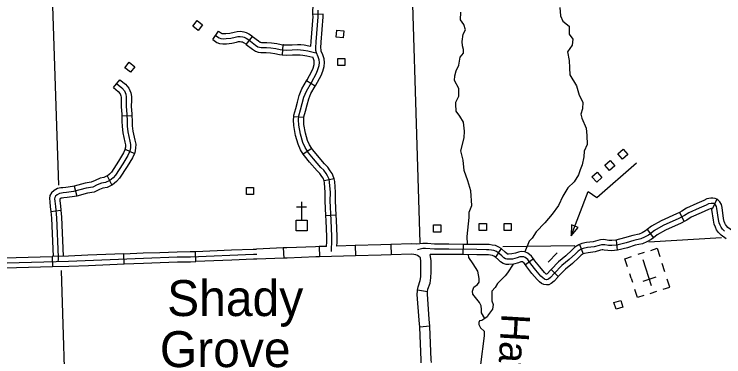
# Model space of a CAD drawing. Extents: x 155 to 3386, y 68 to 2138.
# Drawn here: x 1855.9 to 2154, y 551.2 to 695.1 of the extents above; entities that cross this region are included whole.
import ezdxf

# ---------------------------------------------------------------- set-up
doc = ezdxf.new("R2010")
doc.units = 0
for name, color, linetype in [('Level 24', 7, 'Continuous'), ('Level 31', 7, 'Continuous'), ('Level 32', 7, 'Continuous'), ('Level 35', 7, 'Continuous'), ('Level 5', 7, 'Continuous'), ('Level 56', 7, 'Continuous'), ('Level 57', 7, 'Continuous')]:
    doc.layers.add(name, color=color, linetype=linetype)

msp = doc.modelspace()

# ---------------------------------------------------------------- linework, layer by layer
at = {"layer": 'Level 31'}
for p, q in [((1871.81, 593.39), (1871.92, 589.11)), ((1902.1, 590.24), (1901.93, 594.52)), ((1901.93, 594.52), (1901.93, 594.52)), ((1932.26, 591.21), (1932.09, 595.5))]:
    msp.add_line(p, q, dxfattribs=at)
for points in [[(1797.31, 667.31), (1798.16, 646.01), (1799.06, 609.19), (1799.39, 589), (1803.2, 589.28), (1816.86, 589.87), (1832.07, 590.19), (1878.76, 591.43), (1910.14, 592.71), (1924.39, 593.22), (1929.89, 593.26), (1956.37, 594.32), (1957.8, 594.37)], [(1947.16, 596.1), (1956.29, 596.46), (1957.71, 596.51)], [(1856.73, 592.99), (1871.81, 593.39)], [(1886.86, 593.91), (1878.68, 593.57), (1871.81, 593.39)], [(1901.93, 594.52), (1886.86, 593.91)], [(1901.93, 594.52), (1910.06, 594.85), (1917.02, 595.1)], [(1917.02, 595.1), (1924.34, 595.36), (1929.84, 595.41), (1932.09, 595.5)], [(1932.09, 595.5), (1947.16, 596.1)], [(1841.65, 592.59), (1856.73, 592.99)], [(1902.1, 590.24), (1910.22, 590.57), (1917.17, 590.82)], [(1917.17, 590.82), (1924.44, 591.08), (1929.94, 591.12), (1932.26, 591.21)], [(1947.33, 591.81), (1932.26, 591.21)], [(1957.88, 592.23), (1956.46, 592.18), (1947.33, 591.81)], [(1841.76, 588.31), (1856.84, 588.71)], [(1856.84, 588.71), (1871.92, 589.11)], [(1871.92, 589.11), (1878.83, 589.29), (1887.03, 589.62)], [(1887.03, 589.62), (1902.1, 590.24)]]:
    msp.add_lwpolyline(points, dxfattribs=at)
at = {"layer": 'Level 32'}
for p, q in [((1985.7, 695.14), (1981.42, 695.08)), ((1939.3, 684.45), (1941.71, 687.99)), ((1953.39, 682.46), (1956.03, 685.83)), ((1968.67, 678.03), (1968.89, 682.31)), ((1897.54, 664.33), (1900.28, 667.63)), ((1982.4, 664.92), (1978.71, 667.1)), ((1901.07, 652.4), (1905.35, 652.55)), ((1977.62, 651.78), (1973.34, 652.09)), ((1902.49, 638.45), (1906.39, 636.68)), ((1980.96, 638.72), (1977.35, 636.42)), ((1895, 627.21), (1896.87, 623.36)), ((1990.3, 626.06), (1986.11, 625.19)), ((1881.08, 622.92), (1882.15, 618.77)), ((2151.04, 617.42), (2149.3, 613.51)), ((1871.25, 612.33), (1875.51, 612.76)), ((2135.45, 611.91), (2137.44, 608.11)), ((1991.12, 610.69), (1986.84, 610.47)), ((2121.85, 604.67), (2124.46, 601.27)), ((2108.83, 600.24), (2109.2, 595.97)), ((1968.94, 596.95), (1969.11, 592.67)), ((1984.04, 597.51), (1984.16, 593.23)), ((1999.12, 597.92), (1999.24, 593.63)), ((2014.19, 598.34), (2014.33, 594.06)), ((2044.47, 598.46), (2044.43, 594.17)), ((2060.46, 596.69), (2058.06, 593.14)), ((2093.4, 598.46), (2094.96, 594.47)), ((2074.09, 592.4), (2070.68, 589.8)), ((2081.43, 587.95), (2084.49, 584.94)), ((2029.56, 578.56), (2025.33, 579.28)), ((2030.54, 564.09), (2026.28, 563.66))]:
    msp.add_line(p, q, dxfattribs=at)
for points in [[(1981.42, 695.08), (1981.39, 697.01), (1981.8, 699.97), (1982.19, 701.79), (1982.87, 703.41), (1983.85, 705.04), (1986.16, 708.56), (1987.27, 710.04)], [(1989.21, 595.51), (1989.2, 596.47), (1989.36, 599.46), (1989.36, 601.73), (1989.08, 608.56), (1988.67, 616.75), (1988.71, 620.3), (1988.42, 624.6), (1988.17, 625.81), (1987.54, 627.23), (1986.91, 628.19), (1986, 629.57), (1984.74, 630.78), (1981.61, 634.41), (1979.57, 636.92), (1978.11, 639.22), (1977.15, 641.31), (1976.14, 644.69), (1975.48, 648.57), (1975.39, 650.71), (1975.52, 652.42), (1976.23, 655.01), (1976.94, 657.64), (1977.6, 660.28), (1978.65, 662.78), (1980.82, 666.46), (1982.95, 670.34), (1983.49, 671.85), (1983.99, 673.57), (1984.12, 674.86), (1984.03, 675.95), (1983.57, 677.24), (1982.85, 678.91), (1982.66, 679.87), (1982.61, 681), (1982.78, 683.59), (1983.57, 694.07), (1983.53, 696.88)], [(1980.51, 681.68), (1980.64, 683.74), (1981.43, 694.14), (1981.42, 695.08)], [(1984.79, 680.14), (1984.76, 680.97), (1984.92, 683.44), (1985.72, 694.01), (1985.7, 695.14)], [(1940.51, 686.22), (1942, 685.21), (1942.66, 684.98), (1943.67, 684.85), (1944.98, 684.87), (1946.9, 685.11), (1948.74, 685.54), (1949.81, 685.78), (1950.87, 685.83), (1951.89, 685.7), (1952.55, 685.49), (1953.36, 685.09), (1954.4, 684.39), (1957.22, 682.18), (1958.26, 681.48), (1958.93, 681.24), (1959.63, 681.16), (1960.27, 681.16), (1961.9, 681.16), (1963.74, 681), (1965.79, 680.76), (1967.69, 680.33), (1968.75, 680.17), (1970.3, 680.09), (1972.7, 680.2), (1974.92, 680.25), (1976.12, 680.23), (1977.45, 680.09), (1979.21, 679.77), (1980.87, 679.4), (1982.12, 679.05), (1982.85, 678.91)], [(1941.71, 687.99), (1942.97, 687.14), (1943.15, 687.08), (1943.79, 686.99), (1944.82, 687.01), (1946.52, 687.23), (1948.26, 687.63), (1949.52, 687.91), (1950.96, 687.98), (1952.36, 687.8), (1953.37, 687.48), (1954.43, 686.94), (1955.65, 686.13), (1956.03, 685.83)], [(1956.03, 685.83), (1958.48, 683.91), (1959.24, 683.41), (1959.42, 683.34), (1959.75, 683.3), (1960.27, 683.3), (1961.99, 683.3), (1963.96, 683.13), (1966.16, 682.88), (1968.08, 682.44), (1968.97, 682.31), (1968.89, 682.31)], [(1939.3, 684.45), (1941.03, 683.27), (1942.16, 682.88), (1943.55, 682.7), (1945.13, 682.73), (1947.27, 683), (1949.22, 683.45), (1950.1, 683.65), (1950.79, 683.68), (1951.42, 683.6), (1951.74, 683.5), (1952.28, 683.23), (1953.14, 682.65), (1953.39, 682.46)], [(1953.39, 682.46), (1955.97, 680.44), (1957.29, 679.55), (1958.44, 679.14), (1959.5, 679.02), (1960.27, 679.02), (1961.81, 679.02), (1963.52, 678.87), (1965.43, 678.65), (1967.29, 678.23), (1968.54, 678.04), (1968.67, 678.03)], [(1968.89, 682.31), (1970.31, 682.24), (1972.63, 682.34), (1974.92, 682.4), (1976.25, 682.37), (1977.75, 682.22), (1979.64, 681.87), (1980.51, 681.68)], [(1982.4, 664.92), (1982.68, 665.4), (1984.91, 669.46), (1985.53, 671.18), (1986.1, 673.16), (1986.27, 674.84), (1986.15, 676.4), (1985.57, 678.03), (1984.91, 679.56), (1984.79, 680.13), (1984.79, 680.14)], [(1968.67, 678.03), (1970.29, 677.95), (1972.78, 678.06), (1974.92, 678.11), (1975.99, 678.09), (1977.15, 677.97), (1978.79, 677.67), (1981.3, 677.11)], [(1978.71, 667.1), (1978.96, 667.52), (1980.99, 671.23), (1981.45, 672.51), (1981.88, 673.97), (1981.97, 674.88), (1981.92, 675.5), (1981.58, 676.46), (1981.3, 677.11)], [(1898.91, 665.98), (1901.1, 664.17), (1902.17, 662.89), (1902.81, 661.5), (1902.97, 660.43), (1902.97, 659.09), (1902.91, 656.32), (1903.18, 653.22), (1903.29, 650.23), (1903.34, 648.15), (1903.66, 645.69), (1904.52, 641.85), (1904.78, 640.44), (1904.73, 639.05), (1904.46, 637.61), (1903.66, 635.85), (1901.47, 632.27), (1898.43, 627.52), (1897.42, 626.4), (1896.03, 625.33), (1894.27, 624.48), (1892.56, 624.16), (1890.8, 623.41), (1888.88, 622.5), (1886.16, 622.02), (1880.77, 620.63), (1877.89, 620.24), (1876.5, 620.08), (1875.7, 620.03), (1874.9, 619.87), (1873.99, 619.33), (1873.24, 618.69), (1872.98, 618.21), (1872.87, 617.57), (1872.92, 616.56), (1873.19, 614.42), (1873.67, 609.67), (1874.36, 593.08), (1874.31, 592.12), (1874.26, 591.31)], [(1900.28, 667.63), (1902.62, 665.69), (1903.99, 664.04), (1904.88, 662.12), (1905.11, 660.59), (1905.11, 659.07), (1905.06, 656.39), (1905.32, 653.35), (1905.35, 652.55)], [(1973.34, 652.09), (1973.4, 652.79), (1974.16, 655.58), (1974.86, 658.19), (1975.57, 660.96), (1976.73, 663.74), (1978.71, 667.1)], [(1977.62, 651.78), (1977.64, 652.06), (1978.29, 654.45), (1979.01, 657.1), (1979.64, 659.6), (1980.57, 661.82), (1982.4, 664.92)], [(1897.54, 664.33), (1899.58, 662.64), (1900.34, 661.73), (1900.73, 660.88), (1900.83, 660.27), (1900.83, 659.12), (1900.77, 656.25), (1901.04, 653.09), (1901.07, 652.4)], [(1901.07, 652.4), (1901.15, 650.17), (1901.2, 647.98), (1901.55, 645.32), (1902.42, 641.42), (1902.63, 640.28), (1902.59, 639.29), (1902.4, 638.26), (1902.49, 638.45)], [(1905.35, 652.55), (1905.43, 650.3), (1905.48, 648.32), (1905.77, 646.06), (1906.61, 642.28), (1906.93, 640.6), (1906.86, 638.81), (1906.52, 636.96), (1906.39, 636.68)], [(1977.35, 636.42), (1976.22, 638.19), (1975.13, 640.55), (1974.05, 644.2), (1973.34, 648.35), (1973.25, 650.75), (1973.34, 652.09)], [(1980.96, 638.72), (1979.99, 640.24), (1979.16, 642.06), (1978.23, 645.18), (1977.61, 648.8), (1977.54, 650.68), (1977.62, 651.78)], [(1902.49, 638.45), (1901.76, 636.85), (1899.66, 633.41), (1896.72, 628.82), (1895.96, 627.98), (1894.9, 627.16), (1895, 627.21)], [(1990.3, 626.06), (1990.22, 626.47), (1989.43, 628.25), (1988.7, 629.37), (1987.65, 630.95), (1986.3, 632.25), (1983.25, 635.79), (1981.31, 638.18), (1980.96, 638.72)], [(1906.39, 636.68), (1905.56, 634.84), (1903.29, 631.13), (1900.14, 626.21), (1898.88, 624.82), (1897.16, 623.5), (1896.87, 623.36)], [(1986.11, 625.15), (1985.65, 626.21), (1985.12, 627.01), (1984.34, 628.19), (1983.18, 629.31), (1979.97, 633.04), (1977.83, 635.66), (1977.35, 636.42)], [(1895, 627.21), (1893.59, 626.53), (1891.94, 626.22), (1889.92, 625.36), (1888.22, 624.56), (1885.7, 624.12), (1881.08, 622.92)], [(1896.87, 623.36), (1894.95, 622.42), (1893.18, 622.09), (1891.68, 621.45), (1889.53, 620.44), (1886.61, 619.92), (1882.15, 618.77)], [(1986.84, 610.47), (1986.52, 616.7), (1986.57, 620.24), (1986.29, 624.31), (1986.11, 625.19)], [(1991.12, 610.69), (1990.81, 616.79), (1990.85, 620.36), (1990.54, 624.89), (1990.3, 626.06)], [(1881.08, 622.92), (1880.36, 622.74), (1877.62, 622.37), (1876.3, 622.22), (1875.41, 622.16), (1874.12, 621.9), (1872.74, 621.09), (1871.56, 620.07), (1870.92, 618.93), (1870.72, 617.69), (1870.79, 616.37), (1871.06, 614.18), (1871.25, 612.33)], [(1882.15, 618.77), (1881.18, 618.53), (1878.15, 618.12), (1876.69, 617.95), (1875.98, 617.9), (1875.67, 617.84), (1875.24, 617.58), (1875.02, 617.4), (1875.06, 616.75), (1875.32, 614.66), (1875.51, 612.76)], [(2151.04, 617.42), (2150.34, 617.73), (2149.43, 617.84), (2148.57, 617.84), (2146.95, 617.57), (2145.68, 616.9), (2142.75, 615.61), (2138.29, 613.61), (2136.38, 612.39), (2135.45, 611.91)], [(2157.63, 604.1), (2155.77, 605.56), (2155.14, 606.21), (2154.71, 606.83), (2154.43, 607.36), (2154.2, 608.05), (2153.95, 609.3), (2153.28, 613.94), (2153, 615.19), (2152.31, 616.32), (2151.55, 617.2), (2151.04, 617.42)], [(2154.34, 603.96), (2153.49, 604.84), (2152.87, 605.71), (2152.46, 606.51), (2152.12, 607.49), (2151.84, 608.94), (2151.17, 613.55), (2150.99, 614.38), (2150.58, 615.05), (2150.24, 615.44), (2149.78, 615.64), (2149.31, 615.69), (2148.75, 615.69), (2147.64, 615.51), (2146.61, 614.97), (2143.62, 613.66), (2139.31, 611.72), (2137.46, 610.54), (2135.14, 609.32), (2128.62, 606.36), (2124.88, 604.3), (2122.33, 602.34), (2120.76, 601.43), (2119.19, 600.74), (2116.27, 600.15), (2112.95, 599.11), (2109.06, 598.11), (2106.97, 597.93), (2105.53, 598.01), (2104.03, 598.21), (2103.31, 598.31), (2102.59, 598.26), (2101.64, 598.03), (2099.57, 597.41), (2096.71, 597.08), (2094.96, 596.77), (2094.03, 596.41), (2092.82, 595.63), (2091.69, 594.52), (2089.03, 592.07), (2086.04, 589.57), (2082.74, 586.22), (2081.28, 584.6), (2080.35, 583.82), (2079.94, 583.64), (2079.55, 583.62), (2079.03, 583.67), (2078.67, 583.88), (2078.03, 584.37), (2077.2, 585.16), (2075.06, 587.61), (2073, 590.3), (2071.66, 592.05), (2070.63, 592.95), (2069.96, 593.21), (2069.03, 593.26), (2068.26, 593.16), (2067.18, 592.77), (2065.3, 592.31), (2063.6, 592.18), (2062.85, 592.2), (2062.26, 592.36), (2061.61, 592.82), (2060.79, 593.62), (2059.27, 594.91), (2058.47, 595.45), (2057.46, 595.87), (2056.41, 596.07), (2055.32, 596.2), (2054.34, 596.2), (2050.3, 596.25), (2038.55, 596.38), (2032.41, 596.41), (2028.75, 596.66), (2027.64, 596.66), (2026.43, 596.51), (2025.31, 596.17)], [(1871.25, 612.33), (1871.53, 609.52), (1872.21, 593.4)], [(1875.51, 612.76), (1875.81, 609.82), (1876.49, 593.51)], [(2135.45, 611.91), (2134.2, 611.25), (2127.66, 608.28), (2123.7, 606.09), (2121.85, 604.67)], [(2149.3, 613.51), (2149.21, 613.55), (2149.19, 613.55), (2148.92, 613.55), (2148.33, 613.45), (2147.54, 613.04), (2144.49, 611.7), (2140.33, 609.83), (2138.53, 608.68), (2137.44, 608.11)], [(2154.99, 600.73), (2152.9, 602.37), (2151.83, 603.47), (2151.03, 604.6), (2150.48, 605.67), (2150.05, 606.94), (2149.73, 608.58), (2149.06, 613.17), (2148.97, 613.57), (2148.9, 613.69), (2149.3, 613.51)], [(1987.12, 597.6), (1987.22, 599.52), (1987.22, 601.68), (1986.94, 608.46), (1986.84, 610.47)], [(1991.42, 597.71), (1991.51, 599.4), (1991.51, 601.77), (1991.23, 608.66), (1991.12, 610.69)], [(2137.44, 608.11), (2136.08, 607.4), (2129.58, 604.44), (2126.06, 602.5), (2124.46, 601.27)], [(2121.85, 604.67), (2121.14, 604.12), (2119.79, 603.35), (2118.53, 602.79), (2115.74, 602.22), (2112.36, 601.18), (2108.69, 600.23), (2108.83, 600.24)], [(2108.83, 600.24), (2106.93, 600.08), (2105.73, 600.14), (2104.33, 600.33), (2103.39, 600.47), (2102.26, 600.39), (2101.07, 600.1), (2099.14, 599.52), (2096.4, 599.2), (2094.38, 598.84), (2093.4, 598.46)], [(2124.46, 601.27), (2123.52, 600.55), (2121.73, 599.52), (2119.84, 598.69), (2116.81, 598.07), (2113.53, 597.05), (2109.42, 595.99), (2109.2, 595.97)], [(1968.94, 596.95), (1957.71, 596.51)], [(1984.04, 597.51), (1982.45, 597.47), (1970.45, 597.01), (1968.94, 596.95)], [(1987.12, 597.6), (1984.04, 597.51)], [(1999.12, 597.92), (1991.42, 597.71)], [(2014.19, 598.34), (2009.92, 598.21), (1999.12, 597.92)], [(2024.99, 598.49), (2022.9, 598.62), (2014.19, 598.34)], [(2029.52, 598.76), (2028.83, 598.81), (2027.51, 598.81), (2024.99, 598.49)], [(2044.47, 598.46), (2038.56, 598.52), (2032.49, 598.55), (2029.52, 598.76)], [(2060.46, 596.69), (2059.49, 597.35), (2058.08, 597.93), (2056.74, 598.19), (2055.45, 598.34), (2054.36, 598.34), (2050.32, 598.39), (2044.47, 598.46)], [(2074.09, 592.4), (2073.24, 593.52), (2071.76, 594.81), (2070.42, 595.33), (2068.95, 595.41), (2067.75, 595.25), (2066.56, 594.83), (2064.96, 594.43), (2063.55, 594.32), (2063.18, 594.34), (2062.99, 594.47), (2062.23, 595.21), (2060.56, 596.62), (2060.46, 596.69)], [(2093.4, 598.46), (2093.06, 598.33), (2091.48, 597.32), (2090.21, 596.08), (2087.62, 593.69), (2084.59, 591.15), (2081.43, 587.95)], [(1999.24, 593.63), (1984.16, 593.23)], [(2014.33, 594.06), (2010.05, 593.93), (1999.24, 593.63)], [(2026.57, 592.75), (2025.95, 593.34), (2025.29, 593.8), (2024.64, 594.11), (2023.8, 594.27), (2022.83, 594.33), (2014.33, 594.06)], [(2029.56, 578.56), (2029.74, 579.62), (2030.6, 582.23), (2030.99, 584.41), (2031.04, 586.92), (2031.01, 591.53), (2030.71, 594.27)], [(2044.43, 594.17), (2038.53, 594.24), (2030.71, 594.27)], [(2058.06, 593.14), (2057.45, 593.55), (2056.84, 593.8), (2056.07, 593.95), (2055.2, 594.06), (2054.33, 594.06), (2050.27, 594.11), (2044.43, 594.17)], [(2095.01, 594.49), (2094.16, 593.95), (2093.16, 592.97), (2090.45, 590.46), (2087.5, 588), (2084.49, 584.94)], [(2109.2, 595.97), (2107, 595.78), (2105.32, 595.87), (2103.73, 596.09), (2103.23, 596.16), (2102.92, 596.14), (2102.2, 595.96), (2100.01, 595.31), (2097.02, 594.96), (2095.54, 594.69), (2094.96, 594.47)], [(1969.11, 592.67), (1957.88, 592.23)], [(1984.16, 593.23), (1982.59, 593.19), (1970.61, 592.73), (1969.11, 592.67)], [(2025.33, 579.28), (2025.57, 580.66), (2026.43, 583.29), (2026.71, 584.83), (2026.76, 586.96), (2026.73, 591.28), (2026.57, 592.75)], [(2070.68, 589.8), (2070.09, 590.58), (2069.51, 591.09), (2069.51, 591.09), (2069.12, 591.11), (2068.77, 591.06), (2067.8, 590.72), (2065.64, 590.18), (2063.64, 590.03), (2062.54, 590.07), (2061.33, 590.39), (2060.23, 591.18), (2059.35, 592.03), (2057.97, 593.2), (2058.06, 593.14)], [(2081.43, 587.95), (2081.19, 587.69), (2079.79, 586.15), (2079.52, 585.92), (2079.43, 585.99), (2078.76, 586.64), (2076.72, 588.97), (2074.7, 591.6), (2074.09, 592.4)], [(2084.49, 584.94), (2084.3, 584.75), (2082.76, 583.05), (2081.49, 581.98), (2080.45, 581.53), (2079.51, 581.47), (2078.37, 581.58), (2077.49, 582.08), (2076.63, 582.74), (2075.65, 583.69), (2073.41, 586.26), (2071.3, 588.99), (2070.68, 589.8)], [(2026.28, 563.66), (2025.97, 566.67), (2025.23, 577.44), (2025.29, 579.01), (2025.33, 579.28)], [(2030.54, 564.09), (2030.24, 567.04), (2029.52, 577.51), (2029.56, 578.57), (2029.56, 578.56)], [(2026.89, 548.75), (2026.86, 549.77), (2026.28, 563.67), (2026.28, 563.66)], [(2031.17, 548.86), (2031.14, 549.92), (2030.55, 563.98), (2030.54, 564.09)]]:
    msp.add_lwpolyline(points, dxfattribs=at)
at = {"layer": 'Level 35'}
for points in [[(2085.14, 697.94), (2085.4, 694.5), (2086.41, 692.27), (2089.04, 690.15), (2089.04, 686.81), (2090.55, 684.69), (2090.35, 682.16), (2088.33, 679.38), (2089.04, 675.64), (2089.14, 672.6), (2089.34, 669.67), (2092.17, 665.12), (2093.28, 661.18), (2094.79, 658.25), (2094.69, 655.42), (2093.99, 653.09), (2094.39, 651.48), (2096.21, 647.28), (2096.51, 644.25), (2096.61, 640.41), (2095.39, 637.67), (2095.2, 635.25), (2094.51, 631.94), (2093.64, 629.82), (2093.02, 627.71), (2091.2, 624.78), (2088.53, 622.21), (2086.41, 618.72), (2084.54, 614.73), (2081.86, 611.2), (2078.8, 607.5), (2075.16, 603.77), (2073.56, 601.1), (2072.26, 599.77), (2070.42, 595.33)], [(2045.09, 646.01), (2044.68, 649.75), (2043.07, 652.28), (2041.55, 654.4), (2041.45, 657.33), (2041.45, 658.14), (2042.66, 660.77), (2042.76, 664), (2040.84, 667.27), (2041.05, 669.19), (2041.55, 671.41), (2042.66, 673.74), (2043.29, 677.05), (2044.61, 678.71), (2044.61, 680.38), (2044.3, 681.9), (2044.15, 683.67), (2044.51, 686.75), (2045.47, 688.62), (2044.76, 690.79), (2043.39, 692.71), (2043.6, 696)], [(2046.32, 598.59), (2046.2, 601.8), (2047.01, 609.68), (2047.11, 612.01), (2048.12, 614.84), (2047.81, 620.94), (2046.5, 625.09), (2044.99, 629.43), (2044.48, 633.78), (2043.57, 637.72), (2044.99, 643.18), (2045.09, 646.01)], [(2065.49, 590.17), (2063.17, 586.53), (2062.16, 585.22), (2058.93, 582.09), (2057.92, 580.37), (2056.6, 578.85), (2056.6, 576.02), (2056.6, 574.71), (2057.11, 573.19), (2056.81, 571.27), (2055.19, 568.94), (2054.58, 568.04), (2053.57, 567.33), (2052.16, 569.75), (2052.16, 571.07), (2052.06, 572.58), (2051.45, 574), (2048.62, 577.54), (2048.42, 578.85), (2049.03, 580.47), (2050.54, 581.58), (2051.25, 582.59), (2051.25, 584.11), (2050.75, 587.14), (2048.72, 590.27), (2046.91, 593), (2046.75, 594.09)], [(2053.57, 567.33), (2052.36, 566.47), (2051.35, 566.37), (2051.1, 565.61), (2051.1, 564.85), (2051.85, 563.44), (2053.37, 561.97), (2053.37, 560.81), (2053.34, 560.11)], [(2053.34, 560.11), (2051.79, 547.94)]]:
    msp.add_lwpolyline(points, dxfattribs=at)
at = {"layer": 'Level 5'}
for points in [[(2021.71, 749.3), (2026.33, 599.15)], [(1870.6, 740.89), (1873.36, 656.54)], [(1873.36, 656.54), (1874.45, 623.3)], [(2122.47, 599.56), (2153.08, 601.31)], [(2061.21, 597.63), (2091.49, 598.04)], [(1875.61, 587.46), (1877.76, 519.78)]]:
    msp.add_lwpolyline(points, dxfattribs=at)
at = {"layer": 'Level 56'}
for points in [[(1933.2, 688.3), (1930.87, 690.14), (1932.72, 692.48), (1935.05, 690.64)], [(1991.41, 688.42), (1994.38, 688.19), (1994.15, 685.22), (1991.19, 685.44)], [(1902.36, 672.65), (1904.22, 674.97), (1906.55, 673.1), (1904.69, 670.78)], [(1991.83, 673.54), (1991.83, 676.52), (1994.81, 676.52), (1994.81, 673.54)], [(2111.47, 634.27), (2109.5, 636.5), (2111.73, 638.48), (2113.7, 636.25)], [(2105.98, 629.53), (2104.01, 631.76), (2106.24, 633.74), (2108.22, 631.51)], [(2100.62, 624.54), (2098.65, 626.77), (2100.88, 628.75), (2102.85, 626.52)], [(1953.46, 619.38), (1953.46, 622.36), (1956.44, 622.36), (1956.44, 619.38)], [(2032.1, 603.63), (2032.1, 606.6), (2035.08, 606.6), (2035.08, 603.63)], [(2051.3, 604.31), (2051.3, 607.28), (2054.28, 607.28), (2054.28, 604.31)], [(2061.68, 604.26), (2061.68, 607.24), (2064.66, 607.24), (2064.66, 604.26)], [(2092.81, 605.58), (2090.09, 606.61), (2089.9, 602.01)], [(2110.7, 574.94), (2111.64, 572.12), (2108.81, 571.18), (2107.87, 574)]]:
    msp.add_lwpolyline(points, close=True, dxfattribs=at)
for points in [[(2089.9, 602.01), (2097.01, 620.71), (2100.75, 618.09), (2117.32, 632.78)], [(2084.04, 594.9), (2080.3, 591.03)]]:
    msp.add_lwpolyline(points, dxfattribs=at)
at = {"layer": 'Level 57'}
for p, q in [((1974.48, 614.21), (1978.76, 614.21)), ((1976.62, 616.35), (1976.62, 608.66)), ((2120.63, 595.07), (2117.91, 594.2)), ((2123.66, 581.04), (2120.16, 591.92)), ((2129.25, 586.98), (2128.16, 590.38)), ((2115.11, 584.29), (2114.55, 586.02)), ((2125.5, 584.63), (2120.04, 582.87)), ((2121.91, 586.48), (2121.91, 586.48)), ((2121.91, 586.48), (2121.91, 586.48)), ((2115.11, 584.29), (2115.65, 582.62)), ((2123.15, 577.87), (2125.87, 578.75))]:
    msp.add_line(p, q, dxfattribs=at)
msp.add_lwpolyline([(1974.3, 604.2), (1974.3, 608.66), (1978.93, 608.66), (1978.93, 604.2)], close=True, dxfattribs=at)
for points in [[(2123.37, 595.95), (2126.09, 596.82), (2127.18, 593.42)], [(2113.58, 589.05), (2112.49, 592.45), (2115.21, 593.33)], [(2128.61, 579.63), (2131.33, 580.5), (2130.24, 583.9)], [(2120.45, 577), (2117.73, 576.13), (2116.64, 579.53)]]:
    msp.add_lwpolyline(points, dxfattribs=at)

# ---------------------------------------------------------------- texts
at = {"layer": 'Level 24'}
for s, p in [('Shady', (1920.14, 568.36)), ('Grove', (1917.08, 546.91))]:
    msp.add_text(s, height=15.086, dxfattribs=at).set_placement(p)
at = {"layer": 'Level 35'}
msp.add_text('Hawkins', height=12.069, rotation=266.7062, dxfattribs=at).set_placement((2060.68, 569.62))

doc.saveas('drawing.dxf')
